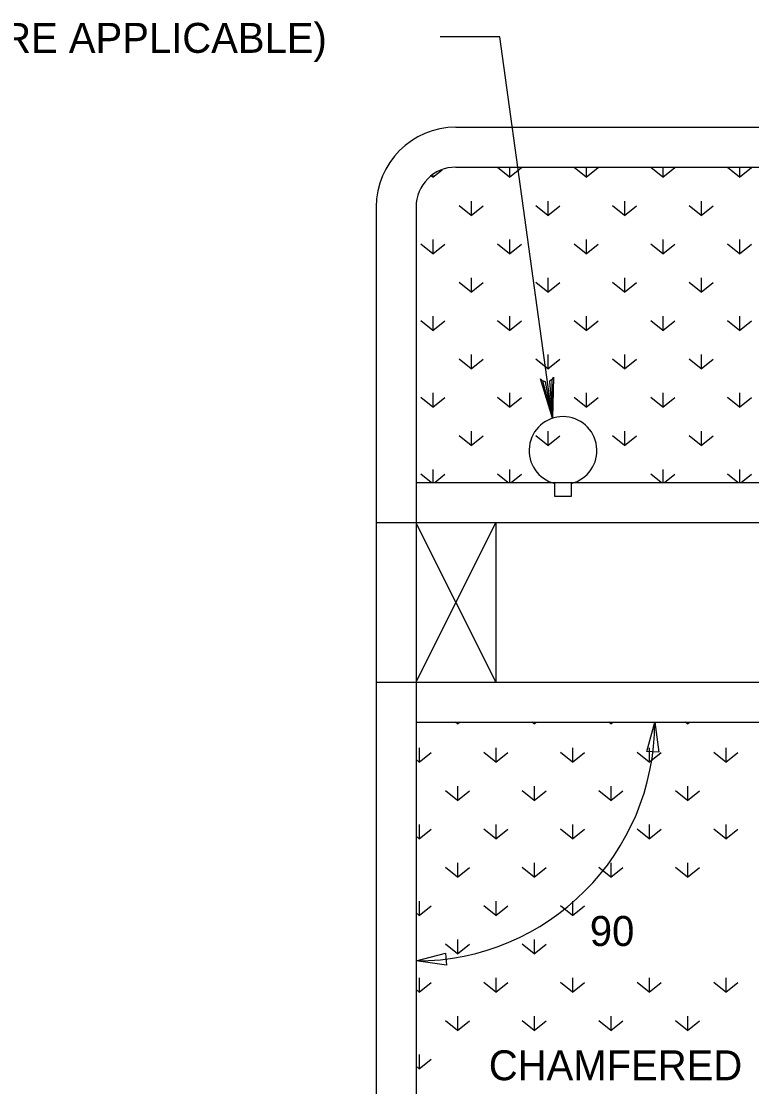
# Model space of a CAD drawing. Extents: x 36 to 940, y -1166 to 1210.
# Drawn here: x 408.6 to 481.8, y -1059.4 to -952.7 of the extents above; entities that cross this region are included whole.
import ezdxf

# ---------------------------------------------------------------- set-up
doc = ezdxf.new("R2010")
doc.units = 0
doc.layers.add('2', color=7, linetype='Continuous')
doc.layers.add('Default', color=7, linetype='Continuous')

msp = doc.modelspace()

# ---------------------------------------------------------------- linework, layer by layer
at = {"layer": '2'}
for p, q in [((462.1, -1000.3), (462.1, -999)), ((463.75, -999), (463.75, -1000.3)), ((463.75, -1000.3), (462.1, -1000.3)), ((456.2, -1002.91), (448.14, -1018.97)), ((448.19, -1002.96), (456.2, -1018.91))]:
    msp.add_line(p, q, dxfattribs=at)
msp.add_lwpolyline([(461.83, -988.58), (461.57, -988.76), (461.88, -992.47), (461.83, -988.58), (461.97, -988.36), (461.88, -992.47), (461.19, -988.82), (460.89, -988.72), (461.88, -992.47), (460.68, -988.54), (460.89, -988.72)], dxfattribs=at)
msp.add_arc((462.93, -995.71), 3.4, 284.1014, 255.8986, dxfattribs=at)
at = {"layer": 'Default'}
for p, q in [((456.6, -954.27), (450.6, -954.27)), ((461.88, -992.47), (456.6, -954.27)), ((452.2, -963.32), (656.79, -963.32)), ((449.89, -968.33), (450.82, -967.59)), ((452.2, -967.32), (656.79, -967.32)), ((457.57, -968.33), (456.37, -967.37)), ((457.57, -967.32), (457.57, -968.33)), ((457.57, -968.33), (458.77, -967.37)), ((465.25, -968.33), (464.05, -967.37)), ((465.25, -967.32), (465.25, -968.33)), ((465.25, -968.33), (466.45, -967.37)), ((472.93, -968.33), (471.73, -967.37)), ((472.93, -967.32), (472.93, -968.33)), ((472.93, -968.33), (474.13, -967.37)), ((480.61, -968.33), (479.41, -967.37)), ((480.61, -967.32), (480.61, -968.33)), ((480.61, -968.33), (481.81, -967.37)), ((449.89, -968.33), (449.76, -968.23)), ((449.89, -968.14), (449.89, -968.33)), ((453.73, -970.73), (453.73, -972.17)), ((461.41, -970.73), (461.41, -972.17)), ((469.09, -970.73), (469.09, -972.17)), ((476.77, -970.73), (476.77, -972.17)), ((444.2, -971.32), (444.2, -994.91)), ((448.2, -971.32), (448.2, -1018.91)), ((453.73, -972.17), (452.53, -971.21)), ((453.73, -972.17), (454.93, -971.21)), ((461.41, -972.17), (460.21, -971.21)), ((461.41, -972.17), (462.61, -971.21)), ((469.09, -972.17), (467.89, -971.21)), ((469.09, -972.17), (470.29, -971.21)), ((476.77, -972.17), (475.57, -971.21)), ((476.77, -972.17), (477.97, -971.21)), ((449.89, -976.01), (448.69, -975.05)), ((449.89, -974.57), (449.89, -976.01)), ((449.89, -976.01), (451.09, -975.05)), ((457.57, -976.01), (456.37, -975.05)), ((457.57, -974.57), (457.57, -976.01)), ((457.57, -976.01), (458.77, -975.05)), ((465.25, -976.01), (464.05, -975.05)), ((465.25, -974.57), (465.25, -976.01)), ((465.25, -976.01), (466.45, -975.05)), ((472.93, -976.01), (471.73, -975.05)), ((472.93, -974.57), (472.93, -976.01)), ((472.93, -976.01), (474.13, -975.05)), ((480.61, -976.01), (479.41, -975.05)), ((480.61, -974.57), (480.61, -976.01)), ((480.61, -976.01), (481.81, -975.05)), ((453.73, -978.41), (453.73, -979.85)), ((461.41, -978.41), (461.41, -979.85)), ((469.09, -978.41), (469.09, -979.85)), ((476.77, -978.41), (476.77, -979.85)), ((453.73, -979.85), (452.53, -978.89)), ((453.73, -979.85), (454.93, -978.89)), ((461.41, -979.85), (460.21, -978.89)), ((461.41, -979.85), (462.61, -978.89)), ((469.09, -979.85), (467.89, -978.89)), ((469.09, -979.85), (470.29, -978.89)), ((476.77, -979.85), (475.57, -978.89)), ((476.77, -979.85), (477.97, -978.89)), ((449.89, -983.69), (448.69, -982.73)), ((449.89, -982.25), (449.89, -983.69)), ((449.89, -983.69), (451.09, -982.73)), ((457.57, -983.69), (456.37, -982.73)), ((457.57, -982.25), (457.57, -983.69)), ((457.57, -983.69), (458.77, -982.73)), ((465.25, -983.69), (464.05, -982.73)), ((465.25, -982.25), (465.25, -983.69)), ((465.25, -983.69), (466.45, -982.73)), ((472.93, -983.69), (471.73, -982.73)), ((472.93, -982.25), (472.93, -983.69)), ((472.93, -983.69), (474.13, -982.73)), ((480.61, -983.69), (479.41, -982.73)), ((480.61, -982.25), (480.61, -983.69)), ((480.61, -983.69), (481.81, -982.73)), ((453.73, -986.09), (453.73, -987.53)), ((461.41, -986.09), (461.41, -987.53)), ((469.09, -986.09), (469.09, -987.53)), ((476.77, -986.09), (476.77, -987.53)), ((453.73, -987.53), (452.53, -986.57)), ((453.73, -987.53), (454.93, -986.57)), ((461.41, -987.53), (460.21, -986.57)), ((461.41, -987.53), (462.61, -986.57)), ((469.09, -987.53), (467.89, -986.57)), ((469.09, -987.53), (470.29, -986.57)), ((476.77, -987.53), (475.57, -986.57)), ((476.77, -987.53), (477.97, -986.57)), ((449.89, -989.93), (449.89, -991.37)), ((457.57, -989.93), (457.57, -991.37)), ((465.25, -989.93), (465.25, -991.37)), ((472.93, -989.93), (472.93, -991.37)), ((480.61, -989.93), (480.61, -991.37)), ((449.89, -991.37), (448.69, -990.41)), ((449.89, -991.37), (451.09, -990.41)), ((457.57, -991.37), (456.37, -990.41)), ((457.57, -991.37), (458.77, -990.41)), ((465.25, -991.37), (464.05, -990.41)), ((465.25, -991.37), (466.45, -990.41)), ((472.93, -991.37), (471.73, -990.41)), ((472.93, -991.37), (474.13, -990.41)), ((480.61, -991.37), (479.41, -990.41)), ((480.61, -991.37), (481.81, -990.41)), ((453.73, -995.21), (452.53, -994.25)), ((453.73, -993.77), (453.73, -995.21)), ((453.73, -995.21), (454.93, -994.25)), ((461.41, -995.21), (460.21, -994.25)), ((461.41, -993.77), (461.41, -995.21)), ((461.41, -995.21), (462.61, -994.25)), ((469.09, -995.21), (467.89, -994.25)), ((469.09, -993.77), (469.09, -995.21)), ((469.09, -995.21), (470.29, -994.25)), ((476.77, -995.21), (475.57, -994.25)), ((476.77, -993.77), (476.77, -995.21)), ((476.77, -995.21), (477.97, -994.25)), ((444.2, -994.91), (444.2, -1106.71)), ((449.89, -997.61), (449.89, -998.91)), ((457.57, -997.61), (457.57, -998.91)), ((472.93, -997.61), (472.93, -998.91)), ((480.61, -997.61), (480.61, -998.91)), ((448.2, -998.91), (507.84, -998.91)), ((449.72, -998.91), (448.69, -998.09)), ((450.07, -998.91), (451.09, -998.09)), ((457.4, -998.91), (456.37, -998.09)), ((457.75, -998.91), (458.77, -998.09)), ((472.76, -998.91), (471.73, -998.09)), ((473.11, -998.91), (474.13, -998.09)), ((480.44, -998.91), (479.41, -998.09)), ((480.79, -998.91), (481.81, -998.09)), ((444.2, -1002.91), (509.49, -1002.91)), ((448.2, -1002.91), (448.2, -1106.71)), ((456.2, -1002.91), (456.2, -1018.91)), ((444.2, -1018.91), (514.56, -1018.91)), ((448.2, -1022.91), (513.58, -1022.91)), ((452.36, -1023.08), (452.15, -1022.91)), ((452.36, -1022.91), (452.36, -1023.08)), ((452.36, -1023.08), (452.57, -1022.91)), ((460.04, -1023.08), (459.83, -1022.91)), ((460.04, -1022.91), (460.04, -1023.08)), ((460.04, -1023.08), (460.25, -1022.91)), ((467.72, -1023.08), (467.51, -1022.91)), ((467.72, -1022.91), (467.72, -1023.08)), ((467.72, -1023.08), (467.93, -1022.91)), ((475.4, -1023.08), (475.19, -1022.91)), ((475.4, -1022.91), (475.4, -1023.08)), ((475.4, -1023.08), (475.61, -1022.91)), ((448.52, -1025.48), (448.52, -1026.92)), ((456.2, -1025.48), (456.2, -1026.92)), ((463.88, -1025.48), (463.88, -1026.92)), ((471.56, -1025.48), (471.56, -1026.92)), ((479.24, -1025.48), (479.24, -1026.92)), ((448.52, -1026.92), (448.2, -1026.67)), ((448.52, -1026.92), (449.72, -1025.96)), ((456.2, -1026.92), (455, -1025.96)), ((456.2, -1026.92), (457.4, -1025.96)), ((463.88, -1026.92), (462.68, -1025.96)), ((463.88, -1026.92), (465.08, -1025.96)), ((471.56, -1026.92), (470.36, -1025.96)), ((471.56, -1026.92), (472.76, -1025.96)), ((479.24, -1026.92), (478.04, -1025.96)), ((479.24, -1026.92), (480.44, -1025.96)), ((452.36, -1030.76), (451.16, -1029.8)), ((452.36, -1029.32), (452.36, -1030.76)), ((452.36, -1030.76), (453.56, -1029.8)), ((460.04, -1030.76), (458.84, -1029.8)), ((460.04, -1029.32), (460.04, -1030.76)), ((460.04, -1030.76), (461.24, -1029.8)), ((467.72, -1030.76), (466.52, -1029.8)), ((467.72, -1029.32), (467.72, -1030.76)), ((467.72, -1030.76), (468.92, -1029.8)), ((475.4, -1030.76), (474.2, -1029.8)), ((475.4, -1029.32), (475.4, -1030.76)), ((475.4, -1030.76), (476.6, -1029.8)), ((448.52, -1033.16), (448.52, -1034.6)), ((448.52, -1034.6), (449.72, -1033.64)), ((456.2, -1034.6), (455, -1033.64)), ((456.2, -1033.16), (456.2, -1034.6)), ((456.2, -1034.6), (457.4, -1033.64)), ((463.88, -1034.6), (462.68, -1033.64)), ((463.88, -1033.16), (463.88, -1034.6)), ((463.88, -1034.6), (465.08, -1033.64)), ((471.56, -1034.6), (470.36, -1033.64)), ((471.56, -1033.16), (471.56, -1034.6)), ((471.56, -1034.6), (472.76, -1033.64)), ((479.24, -1034.6), (478.04, -1033.64)), ((479.24, -1033.16), (479.24, -1034.6)), ((479.24, -1034.6), (480.44, -1033.64)), ((448.52, -1034.6), (448.2, -1034.35)), ((452.36, -1037), (452.36, -1038.44)), ((460.04, -1037), (460.04, -1038.44)), ((467.72, -1037), (467.72, -1038.44)), ((475.4, -1037), (475.4, -1038.44)), ((452.36, -1038.44), (451.16, -1037.48)), ((452.36, -1038.44), (453.56, -1037.48)), ((460.04, -1038.44), (458.84, -1037.48)), ((460.04, -1038.44), (461.24, -1037.48)), ((467.72, -1038.44), (466.52, -1037.48)), ((467.72, -1038.44), (468.92, -1037.48)), ((475.4, -1038.44), (474.2, -1037.48)), ((475.4, -1038.44), (476.6, -1037.48)), ((448.52, -1040.84), (448.52, -1042.28)), ((448.52, -1042.28), (449.72, -1041.32)), ((456.2, -1042.28), (455, -1041.32)), ((456.2, -1040.84), (456.2, -1042.28)), ((456.2, -1042.28), (457.4, -1041.32)), ((463.88, -1042.28), (462.68, -1041.32)), ((463.88, -1040.84), (463.88, -1042.28)), ((463.88, -1042.28), (465.08, -1041.32)), ((448.52, -1042.28), (448.2, -1042.03)), ((452.36, -1044.68), (452.36, -1046.12)), ((460.04, -1044.68), (460.04, -1046.12)), ((452.36, -1046.12), (451.16, -1045.16)), ((452.36, -1046.12), (453.56, -1045.16)), ((460.04, -1046.12), (458.84, -1045.16)), ((460.04, -1046.12), (461.24, -1045.16)), ((448.52, -1048.52), (448.52, -1049.96)), ((448.52, -1049.96), (449.72, -1049)), ((456.2, -1049.96), (455, -1049)), ((456.2, -1048.52), (456.2, -1049.96)), ((456.2, -1049.96), (457.4, -1049)), ((463.88, -1049.96), (462.68, -1049)), ((463.88, -1048.52), (463.88, -1049.96)), ((463.88, -1049.96), (465.08, -1049)), ((471.56, -1049.96), (470.36, -1049)), ((471.56, -1048.52), (471.56, -1049.96)), ((471.56, -1049.96), (472.76, -1049)), ((479.24, -1049.96), (478.04, -1049)), ((479.24, -1048.52), (479.24, -1049.96)), ((479.24, -1049.96), (480.44, -1049)), ((448.52, -1049.96), (448.2, -1049.71)), ((452.36, -1053.8), (451.16, -1052.84)), ((452.36, -1052.36), (452.36, -1053.8)), ((452.36, -1053.8), (453.56, -1052.84)), ((460.04, -1053.8), (458.84, -1052.84)), ((460.04, -1052.36), (460.04, -1053.8)), ((460.04, -1053.8), (461.24, -1052.84)), ((467.72, -1053.8), (466.52, -1052.84)), ((467.72, -1052.36), (467.72, -1053.8)), ((467.72, -1053.8), (468.92, -1052.84)), ((475.4, -1053.8), (474.2, -1052.84)), ((475.4, -1052.36), (475.4, -1053.8)), ((475.4, -1053.8), (476.6, -1052.84)), ((448.52, -1056.2), (448.52, -1057.64)), ((448.52, -1057.64), (448.2, -1057.39)), ((448.52, -1057.64), (449.72, -1056.68))]:
    msp.add_line(p, q, dxfattribs=at)
for points in [[(471.35, -1025.87), (472.14, -1022.91), (472.55, -1025.94)], [(451.24, -1047.25), (448.2, -1046.84), (451.16, -1046.06)]]:
    msp.add_lwpolyline(points, close=True, dxfattribs=at)
for centre, radius, start, end in [((452.2, -971.32), 8, 90, 180), ((452.2, -971.32), 4, 90, 180), ((753.46, -1339.64), 376.8, 122.5261, 142.2884), ((448.2, -1022.91), 23.93, 270, 0), ((753.46, -1339.64), 372.8, 124.6158, 142.2884)]:
    msp.add_arc(centre, radius, start, end, dxfattribs=at)

# ---------------------------------------------------------------- texts
for s, p in [('(WHERE APPLICABLE)', (396.01, -955.87)), ('90', (465.62, -1045.34)), ('CHAMFERED', (455.49, -1058.79))]:
    msp.add_text(s, height=3, dxfattribs=at).set_placement(p)

doc.saveas('drawing.dxf')
